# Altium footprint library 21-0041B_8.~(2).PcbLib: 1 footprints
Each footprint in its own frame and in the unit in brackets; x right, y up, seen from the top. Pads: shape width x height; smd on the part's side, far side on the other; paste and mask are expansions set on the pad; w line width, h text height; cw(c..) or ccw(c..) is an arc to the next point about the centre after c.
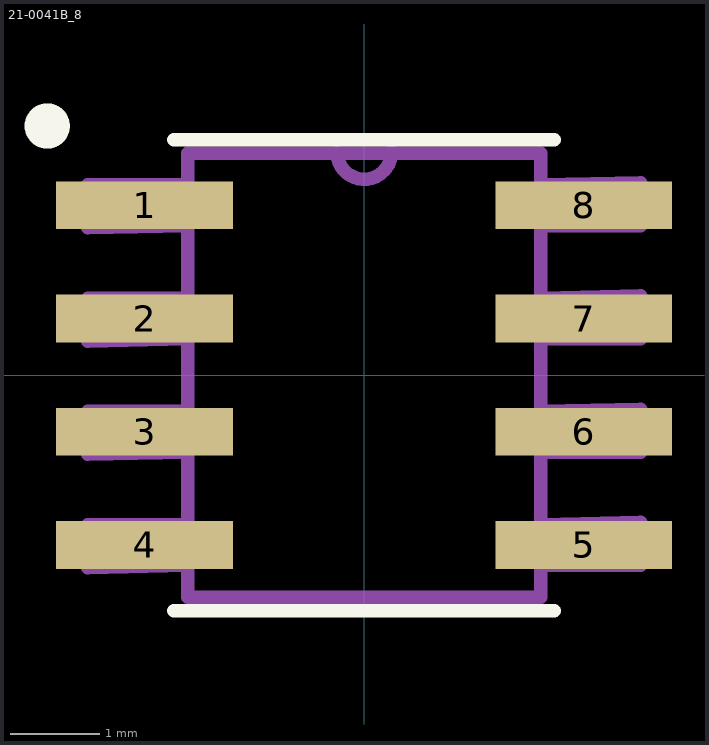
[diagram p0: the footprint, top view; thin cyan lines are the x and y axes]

## 21-0041B_8 [mil]
pads (8):
  rect 78x21 smd: 1(-97,75) 2(-97,25) 3(-97,-25) 4(-97,-75) 5(97,-75) 6(97,-25) 7(97,25) 8(97,75)
Top Overlay:
  circle w10: c-140,110 r5
  lines w6: -84,-104 84,-104 ; -84,104 84,104
Assembly Top:
  lines w6: -12,98.08 ccw(c0,98.5) 12,98.92 ; -122,-85 -78,-84 -78,-66 -122,-66 -122,-85 ; -122,-35 -78,-34 -78,-16 -122,-16 -122,-35 ; -122,15 -78,16 -78,34 -122,34 -122,15 ; -122,65 -78,66 -78,84 -122,84 -122,65 ; -78,-98 -78,98 -12,98 78,98 78,-98 -78,-98 ; 78,-84 122,-84 122,-65 78,-66 78,-84 ; 78,-34 122,-34 122,-15 78,-16 78,-34 ; 78,16 122,16 122,35 78,34 78,16 ; 78,66 122,66 122,85 78,84 78,66
3D body "step_temp.STEP": height 68.9, standoff 0, extent -118.11,-96.46 118.11,96.46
